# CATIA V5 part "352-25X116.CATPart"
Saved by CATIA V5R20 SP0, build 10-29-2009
Part number: 352-25X116
Definition: NONE
Nomenclature: 352-25X116
Source: Unknown
Description: 352-25X116
Bounding box of the stored display mesh (mm): x 0 to 116, y -17 to 17, z -17 to 17
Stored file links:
  C:\Users\Utente\Desktop\IO LAVORO\3D X SITO CF\X SITO\PLASTICA\352\352-25X116.CATPart

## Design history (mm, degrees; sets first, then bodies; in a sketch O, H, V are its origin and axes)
Body1 "352-25X116" (main body)
  Solid1: solid without history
